(* Logix 5000 project; controller Motion_Axis_AOIs_AMCI_RSLogix_V31 vendor 1 type 14 code 108 rev 31.11; software revision 31.02 *)

TASK MainTask (continuous, watchdog 500 ms) : MainProgram

MODULES
   Local : vendor 1 type 14 code 108 (Compact 0, rev 31.11)
      AMCI_SD31045E2 : vendor 10 type 12 code 27 (Ethernet 192.168.0.53, rev 1.2, StandardDataDriven RPI 8 ms)
      AMCI_SMD23E2 : vendor 10 type 12 code 29 (Ethernet 192.168.0.50, rev 1.6, StandardDataDriven RPI 8 ms)
      AMCI_SMD17E2 : vendor 10 type 12 code 45 (Ethernet 192.168.0.54, rev 1.18, StandardDataDriven RPI 8 ms)
      AMCI_SMD34E2 : vendor 10 type 12 code 28 (Ethernet 192.168.0.55, rev 1.6, StandardDataDriven RPI 8 ms)
      AMCI_SD17060E2 : vendor 10 type 12 code 26 (Ethernet 192.168.0.52, rev 1.2, StandardDataDriven RPI 8 ms)
      AMCI_SD4840E2 : vendor 10 type 12 code 40 (Ethernet 192.168.0.51, rev 1.21, StandardDataDriven RPI 8 ms)
      AMCI_SV160E2 : vendor 10 type 12 code 47 (Ethernet 192.168.0.56, rev 1.31, StandardDataDriven RPI 8 ms)
      AMCI_SV400E2 : vendor 10 type 12 code 51 (Ethernet 192.168.0.57, rev 1.31, StandardDataDriven RPI 8 ms)
END_MODULES

TYPE AMCI_Motion_Axis_Input_Data :
STRUCT
   Moving_CW : BOOL;
   Moving_CCW : BOOL;
   In_Hold_State : BOOL;
   Stopped : BOOL;
   At_Home : BOOL;
   Accelerating : BOOL;
   Decelerating : BOOL;
   Move_Complete : BOOL;
   Status_Word_0_Bit_8 : BOOL;
   Status_Word_0_Bit_9 : BOOL;
   Position_Invalid : BOOL;
   Input_Error : BOOL;
   Command_Error : BOOL;
   Configuration_Error : BOOL;
   Module_OK : BOOL;
   Mode_Flag : BOOL;
   IN1_Active : BOOL;
   IN2_Active : BOOL;
   IN3_Active : BOOL;
   IN4_Active : BOOL;
   Status_Word_1_Bit_4 : BOOL;
   Status_Word_1_Bit_5 : BOOL;
   Connection_Was_Lost : BOOL;
   Driver_Fault : BOOL;
   Status_Word_1_Bit_8 : BOOL;
   Invalid_Jog_Change : BOOL;
   Status_Word_1_Bit_10 : BOOL;
   Heartbeat_Bit : BOOL;
   Status_Word_1_Bit_12 : BOOL;
   Status_Word_1_Bit_13 : BOOL;
   Stall_Detected : BOOL;
   Drive_Is_Enabled : BOOL;
   Motor_Position : DINT;
   Encoder_Position : DINT;
   Trapped_Encoder_Position : DINT;
   Input_Word_8 : INT;
   Input_Word_9 : INT;
END_STRUCT
END_TYPE

TYPE AMCI_Motion_Axis_Output_Data :
STRUCT
   Control_Word_0 : INT;
   Control_Word_1 : INT;
   Position_or_Distance : DINT;
   Programmed_Speed : DINT;
   Acceleration : INT;
   Deceleration : INT;
   Output_Word_8 : INT;
   Output_Word_9 : INT;
END_STRUCT
END_TYPE

ADD_ON_INSTRUCTION AMCI_MA_Preset_Encoder   (* revision 2.1, vendor AMCI, ExecuteEnableInFalse *)
// AMCI Preset Encoder Position.  Will not work on SVXXXE2
// Revision note:
// 3/6/23: Added Save in Flash bit
// 11/17/23 V2.1 Reset output word 0 to 0 when the rung goes false.
// Help:
// MOTION_AXIS_PRESET_ENCODER: Preset Encoder Position to a value.  This AOI will only work on AMCI SD and SMD devices that have an encoder.   This AOI WILL NOT WORK  with SVXXXE2 units
// Note: This instruction will maintain the motion device’s current enabled state.  That is, if the device is enabled,
//            it will remain enabled.  If it is disabled, it will remain disabled.
// AXIS INPUT DATA:  Input data from AMCI motion device.   Uses the AMCI_Motion_Axis_Input_Data User Defined Data Type.
// AXIS OUTPUT DATA; Output data from the AOI to the AMCI motion device.   Uses the AMCI_Motion_Axis_Output_Data User Defined Data Type.
// POSITION: Position to which the Encoder Position is to be set.
// SAVE_IN_FLASH_0_NO_1_YES:  Saves the offset encoder value in the flash memory.    Only used on the SMDXXE2 units with Absolute Encoders.  Must be zero on all other units.
// EN (Enable) Set when rung is true, Reset when rung is false
// DN (Done) Set when command is sent to the motion device.  Reset when the rung is false.
// ER (Error) Set when a command or input error failed to clear.  Reset when the rung is false.
VAR_IN_OUT
   Axis_Input_Data : AMCI_Motion_Axis_Input_Data; {required}
   Axis_Output_Data : AMCI_Motion_Axis_Output_Data; {required}
END_VAR
VAR_INPUT
   Position : DINT; {required}
   save_in_flash_0_no_1_yes : BOOL; {required}
END_VAR
VAR_OUTPUT
   EN : BOOL; {visible}   // set when rung with AOI is true
   DN : BOOL; {access Read Only, visible}   // set when preset motor position command sent to motion axis
   ER : BOOL; {access Read Only, visible}   // set when input, command, or configuraiton error
END_VAR
VAR
   command_data_block : INT[10];
        [2]   // Upper Target Position
        [4]   // Upper Programmed Speed
        [5]   // Lower Programmed Speed
        [1]   // Command Bits LSW
        [0]   // Command Bits MSW
        [3]   // Lower Target Position
END_VAR

ROUTINE EnableInFalse   (* ladder *)
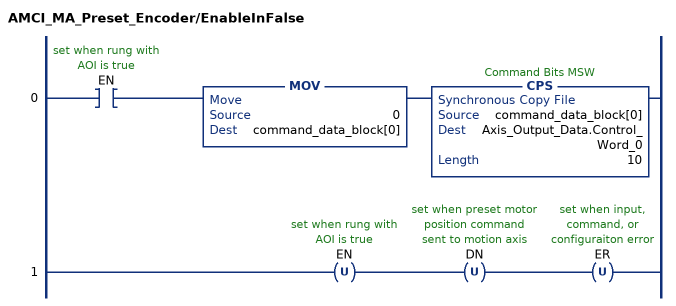
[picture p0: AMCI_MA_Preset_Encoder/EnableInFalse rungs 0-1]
   0: XIC(EN)MOV(0,command_data_block[0])CPS(command_data_block[0],Axis_Output_Data.Control_Word_0,10);
   1: OTU(EN)OTU(DN)OTU(ER);
END_ROUTINE

ROUTINE Logic   (* ladder *)
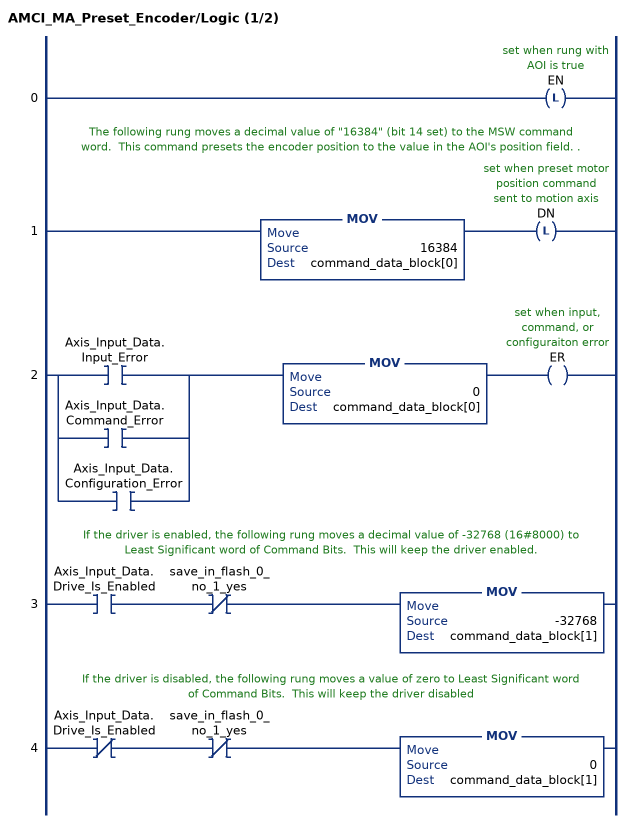
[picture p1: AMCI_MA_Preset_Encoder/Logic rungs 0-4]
   0: OTL(EN);
   // The following rung moves a decimal value of "16384" (bit 14 set) to the MSW command word.  This command presets the encoder position to the value in the AOI's position field. .
   1: MOV(16384,command_data_block[0])OTL(DN);
   2: [XIC(Axis_Input_Data.Input_Error) ,XIC(Axis_Input_Data.Command_Error) ,XIC(Axis_Input_Data.Configuration_Error) ]MOV(0,command_data_block[0])OTE(ER);
   // If the driver is enabled, the following rung moves a decimal value of -32768 (16#8000) to Least Significant word of Command Bits.  This will keep the driver enabled.
   3: XIC(Axis_Input_Data.Drive_Is_Enabled)XIO(save_in_flash_0_no_1_yes)MOV(-32768,command_data_block[1]);
   // If the driver is disabled, the following rung moves a value of zero to Least Significant word of Command Bits.  This will keep the driver disabled
   4: XIO(Axis_Input_Data.Drive_Is_Enabled)XIO(save_in_flash_0_no_1_yes)MOV(0,command_data_block[1]);
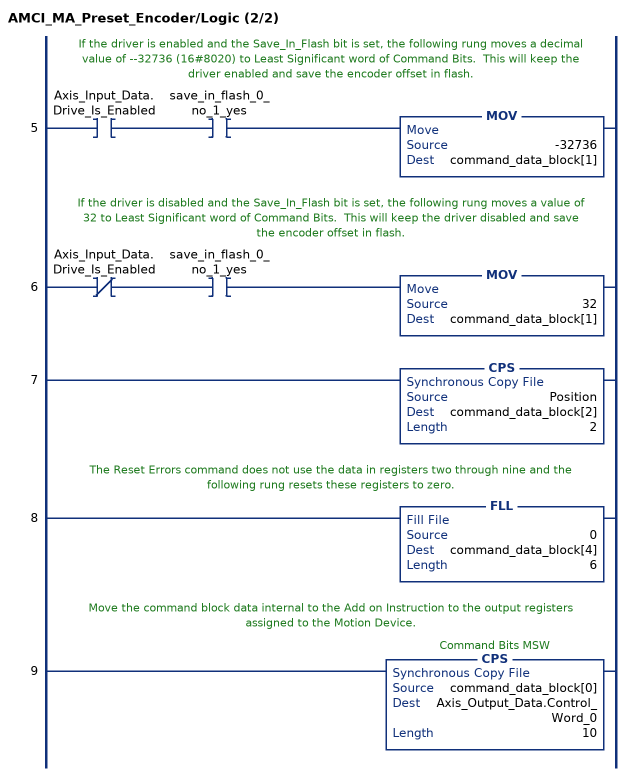
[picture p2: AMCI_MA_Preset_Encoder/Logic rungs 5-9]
   // If the driver is enabled and the Save_In_Flash bit is set, the following rung moves a decimal value of --32736 (16#8020) to Least Significant word of Command Bits.  This will keep the driver enabled and save the encoder offset in flash.
   5: XIC(Axis_Input_Data.Drive_Is_Enabled)XIC(save_in_flash_0_no_1_yes)MOV(-32736,command_data_block[1]);
   // If the driver is disabled and the Save_In_Flash bit is set, the following rung moves a value of 32 to Least Significant word of Command Bits.  This will keep the driver disabled and save the encoder offset in flash.
   6: XIO(Axis_Input_Data.Drive_Is_Enabled)XIC(save_in_flash_0_no_1_yes)MOV(32,command_data_block[1]);
   7: CPS(Position,command_data_block[2],2);
   // The Reset Errors command does not use the data in registers two through nine and the following rung resets these registers to zero.
   8: FLL(0,command_data_block[4],6);
   // Move the command block data internal to the Add on Instruction to the output registers assigned to the Motion Device.
   9: CPS(command_data_block[0],Axis_Output_Data.Control_Word_0,10);
END_ROUTINE
END_ADD_ON_INSTRUCTION

ADD_ON_INSTRUCTION AMCI_MA_Program_Assembed_Move   (* revision 1.0, vendor AMCI, ExecuteEnableInFalse *)
// Program Assembled Moves for SD and SMD devices.  Will not work with SV integrated servo devices.
// Help:
// MOTION AXIS PROGRAM ASSEMBLED MOVE
// This AOIs will only work with the SD and SMD motion devices.  The SV motion devices do not support Assembled Moves.
// Up to 16 segments can be programmed into an Assembled Move.
// AXIS INPUT DATA:  Input data from AMCI motion device.   Uses the AMCI_Motion_Axis_Input_Data User Defined Data Type.
// AXIS OUTPUT DATA; Output data from the AOI to the AMCI motion device.   Uses the AMCI_Motion_Axis_Output_Data User Defined Data Type.
// NUMBER_OF_SEGMENTS: Number of Move segments, range of 2 to 16.
// SEGMENT_X_DISTANCE: The relative number of steps to move in the “X” segment.
// SEGMENT_X_PROGRAMMED_SPEED:   The target speed of the “X” segment
// SEGMENT_X_ACCELERATION: If the programmed speed of the previous segment is less than the                                                      programmed speed of the current segment, the acceleration is used as the                                                      rate of change of the speed between the two segments.
// SEGMENT_X_DECELERATION: If the programmed speed of the previous segment is greater than the                                                       programmed speed of the current segment, the deceleration is used as the                                                       rate of change of the speed between the two segments.
// EN (Enable) Set when rung is true, Reset when rung is false
// ER (Error) Set when a command or input error failed to clear.  Reset when the rung is false.
// ASSEMBLED_MOVE_PROGRAMMED: Set when All segments of the Assembled Move have been                                                                 programmed.  Reset when the rung is false.
VAR_IN_OUT
   Axis_Input_data : AMCI_Motion_Axis_Input_Data; {required}
   Axis_Output_data : AMCI_Motion_Axis_Output_Data; {required}
END_VAR
VAR_INPUT
   Number_of_Segments : DINT; {required}
   Segment_1_Distance : DINT; {required}
   Segment_1_Programmed_Speed : DINT; {required}
   Segment_1_Acceleration : INT; {required}
   Segment_1_Deceleration : INT; {required}
   Segment_2_Distance : DINT; {required}
   Segment_2_Programmed_Speed : DINT; {required}
   Segment_2_Acceleration : INT; {required}
   Segment_2_Deceleration : INT; {required}
   Segment_3_Distance : DINT; {required}
   Segment_3_Programmed_Speed : DINT; {required}
   Segment_3_Acceleration : INT; {required}
   Segment_3_Deceleration : INT; {required}
   Segment_4_Distance : DINT; {required}
   Segment_4_Programmed_Speed : DINT; {required}
   Segment_4_Acceleration : INT; {required}
   Segment_4_Deceleration : INT; {required}
   Segment_5_Distance : DINT; {required}
   Segment_5_Programmed_Speed : DINT; {required}
   Segment_5_Acceleration : INT; {required}
   Segment_5_Deceleration : INT; {required}
   Segment_6_Distance : DINT; {required}
   Segment_6_Programmed_Speed : DINT; {required}
   Segment_6_Acceleration : INT; {required}
   Segment_6_Deceleration : INT; {required}
   Segment_7_Distance : DINT; {required}
   Segment_7_Programmed_Speed : DINT; {required}
   Segment_7_Acceleration : INT; {required}
   Segment_7_Deceleration : INT; {required}
   Segment_8_Distance : DINT; {required}
   Segment_8_Programmed_Speed : DINT; {required}
   Segment_8_Acceleration : INT; {required}
   Segment_8_Deceleration : INT; {required}
   Segment_9_Distance : DINT; {required}
   Segment_9_Programmed_Speed : DINT; {required}
   Segment_9_Acceleration : INT; {required}
   Segment_9_Deceleration : INT; {required}
   Segment_10_Distance : DINT; {required}
   Segment_10_Programmed_Speed : DINT; {required}
   Segment_10_Acceleration : INT; {required}
   Segment_10_Deceleration : INT; {required}
   Segment_11_Distance : DINT; {required}
   Segment_11_Programmed_Speed : DINT; {required}
   Segment_11_Acceleration : INT; {required}
   Segment_11_Deceleration : INT; {required}
   Segment_12_Distance : DINT; {required}
   Segment_12_Programmed_Speed : DINT; {required}
   Segment_12_Acceleration : INT; {required}
   Segment_12_Deceleration : INT; {required}
   Segment_13_Distance : DINT; {required}
   Segment_13_Programmed_Speed : DINT; {required}
   Segment_13_Acceleration : INT; {required}
   Segment_13_Deceleration : INT; {required}
   Segment_14_Distance : DINT; {required}
   Segment_14_Programmed_Speed : DINT; {required}
   Segment_14_Acceleration : INT; {required}
   Segment_14_Deceleration : INT; {required}
   Segment_15_Distance : DINT; {required}
   Segment_15_Programmed_Speed : DINT; {required}
   Segment_15_Acceleration : INT; {required}
   Segment_15_Deceleration : INT; {required}
   Segment_16_Distance : DINT; {required}
   Segment_16_Programmed_Speed : DINT; {required}
   Segment_16_Acceleration : INT; {required}
   Segment_16_Deceleration : INT; {required}
END_VAR
VAR_OUTPUT
   EN : BOOL; {access Read Only, visible}
   ER : BOOL; {access Read Only, visible}
   Assembled_Move_Programmed : BOOL; {access Read Only, visible}
END_VAR
VAR
   command_data_block : INT[10];
        [5]   // Lower Programmed Speed
        [0]   // Command Bits MSW
        [2]   // Upper Target Position
        [4]   // Upper Programmed Speed
        [1]   // Command Bits LSW
        [3]   // Lower Target Position
   Assembled_Move_setup : INT[10] := ([0] := 2048, [1] := -32768); {access None}
   Assembled_Move_counter : COUNTER := (PRE := 5); {access None}
        .ACC   // Controls which segment is sent to the Motion Axis Device
   comment_coil : BOOL; {access None}
END_VAR

ROUTINE EnableInFalse   (* ladder *)
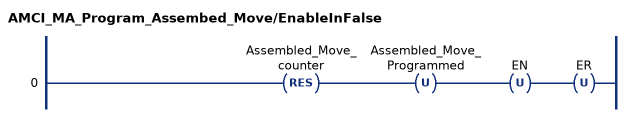
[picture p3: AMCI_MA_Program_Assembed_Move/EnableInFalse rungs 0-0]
   0: RES(Assembled_Move_counter)OTU(Assembled_Move_Programmed)OTU(EN)OTU(ER);
END_ROUTINE

ROUTINE Logic   (* ladder *)
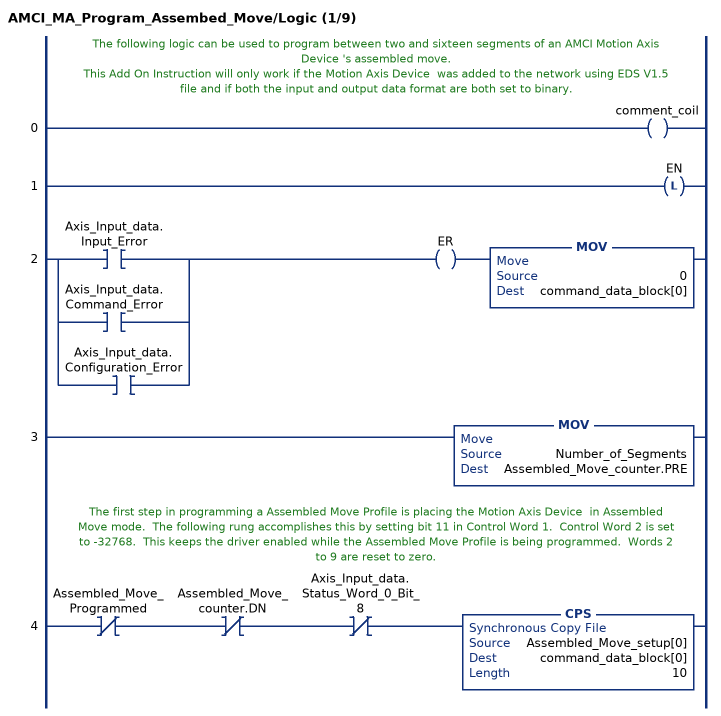
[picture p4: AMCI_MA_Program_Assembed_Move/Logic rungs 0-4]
   // The following logic can be used to program between two and sixteen segments of an AMCI Motion Axis Device 's assembled move.
   // This Add On Instruction will only work if the Motion Axis Device  was added to the network using EDS V1.5 file and if both the input and output data format are both set to binary.
   0: OTE(comment_coil);
   1: OTL(EN);
   2: [XIC(Axis_Input_data.Input_Error) ,XIC(Axis_Input_data.Command_Error) ,XIC(Axis_Input_data.Configuration_Error) ]OTE(ER)MOV(0,command_data_block[0]);
   3: MOV(Number_of_Segments,Assembled_Move_counter.PRE);
   // The first step in programming a Assembled Move Profile is placing the Motion Axis Device  in Assembled Move mode.  The following rung accomplishes this by setting bit 11 in Control Word 1.  Control Word 2 is set to -32768.  This keeps the driver enabled while the Assembled Move Profile is being programmed.  Words 2 to 9 are reset to zero.
   4: XIO(Assembled_Move_Programmed)XIO(Assembled_Move_counter.DN)XIO(Axis_Input_data.Status_Word_0_Bit_8)CPS(Assembled_Move_setup[0],command_data_block[0],10);
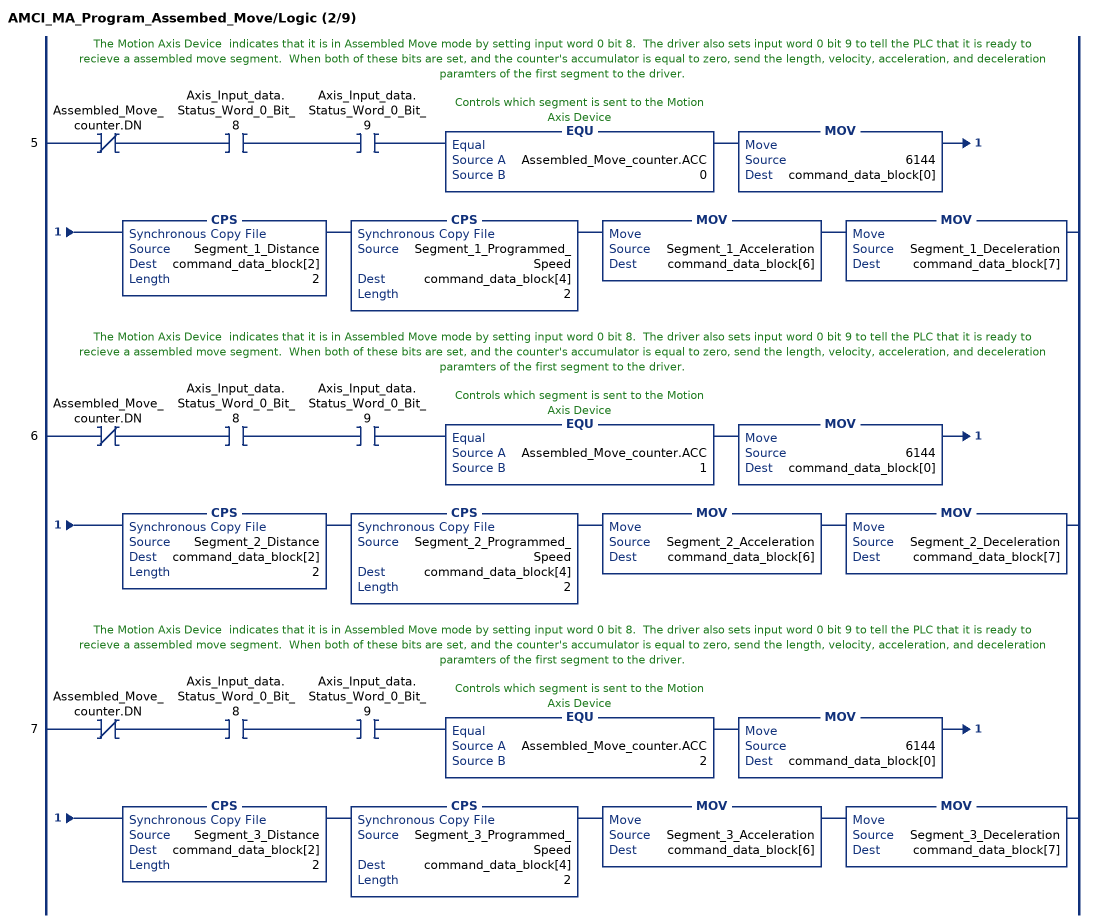
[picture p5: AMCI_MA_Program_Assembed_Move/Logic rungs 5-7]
   // The Motion Axis Device  indicates that it is in Assembled Move mode by setting input word 0 bit 8.  The driver also sets input word 0 bit 9 to tell the PLC that it is ready to recieve a assembled move segment.  When both of these bits are set, and the counter's accumulator is equal to zero, send the length, velocity, acceleration, and deceleration paramters of the first segment to the driver.
   5: XIO(Assembled_Move_counter.DN)XIC(Axis_Input_data.Status_Word_0_Bit_8)XIC(Axis_Input_data.Status_Word_0_Bit_9)EQU(Assembled_Move_counter.ACC,0)MOV(6144,command_data_block[0])CPS(Segment_1_Distance,command_data_block[2],2)CPS(Segment_1_Programmed_Speed,command_data_block[4],2)MOV(Segment_1_Acceleration,command_data_block[6])MOV(Segment_1_Deceleration,command_data_block[7]);
   // The Motion Axis Device  indicates that it is in Assembled Move mode by setting input word 0 bit 8.  The driver also sets input word 0 bit 9 to tell the PLC that it is ready to recieve a assembled move segment.  When both of these bits are set, and the counter's accumulator is equal to zero, send the length, velocity, acceleration, and deceleration paramters of the first segment to the driver.
   6: XIO(Assembled_Move_counter.DN)XIC(Axis_Input_data.Status_Word_0_Bit_8)XIC(Axis_Input_data.Status_Word_0_Bit_9)EQU(Assembled_Move_counter.ACC,1)MOV(6144,command_data_block[0])CPS(Segment_2_Distance,command_data_block[2],2)CPS(Segment_2_Programmed_Speed,command_data_block[4],2)MOV(Segment_2_Acceleration,command_data_block[6])MOV(Segment_2_Deceleration,command_data_block[7]);
   // The Motion Axis Device  indicates that it is in Assembled Move mode by setting input word 0 bit 8.  The driver also sets input word 0 bit 9 to tell the PLC that it is ready to recieve a assembled move segment.  When both of these bits are set, and the counter's accumulator is equal to zero, send the length, velocity, acceleration, and deceleration paramters of the first segment to the driver.
   7: XIO(Assembled_Move_counter.DN)XIC(Axis_Input_data.Status_Word_0_Bit_8)XIC(Axis_Input_data.Status_Word_0_Bit_9)EQU(Assembled_Move_counter.ACC,2)MOV(6144,command_data_block[0])CPS(Segment_3_Distance,command_data_block[2],2)CPS(Segment_3_Programmed_Speed,command_data_block[4],2)MOV(Segment_3_Acceleration,command_data_block[6])MOV(Segment_3_Deceleration,command_data_block[7]);
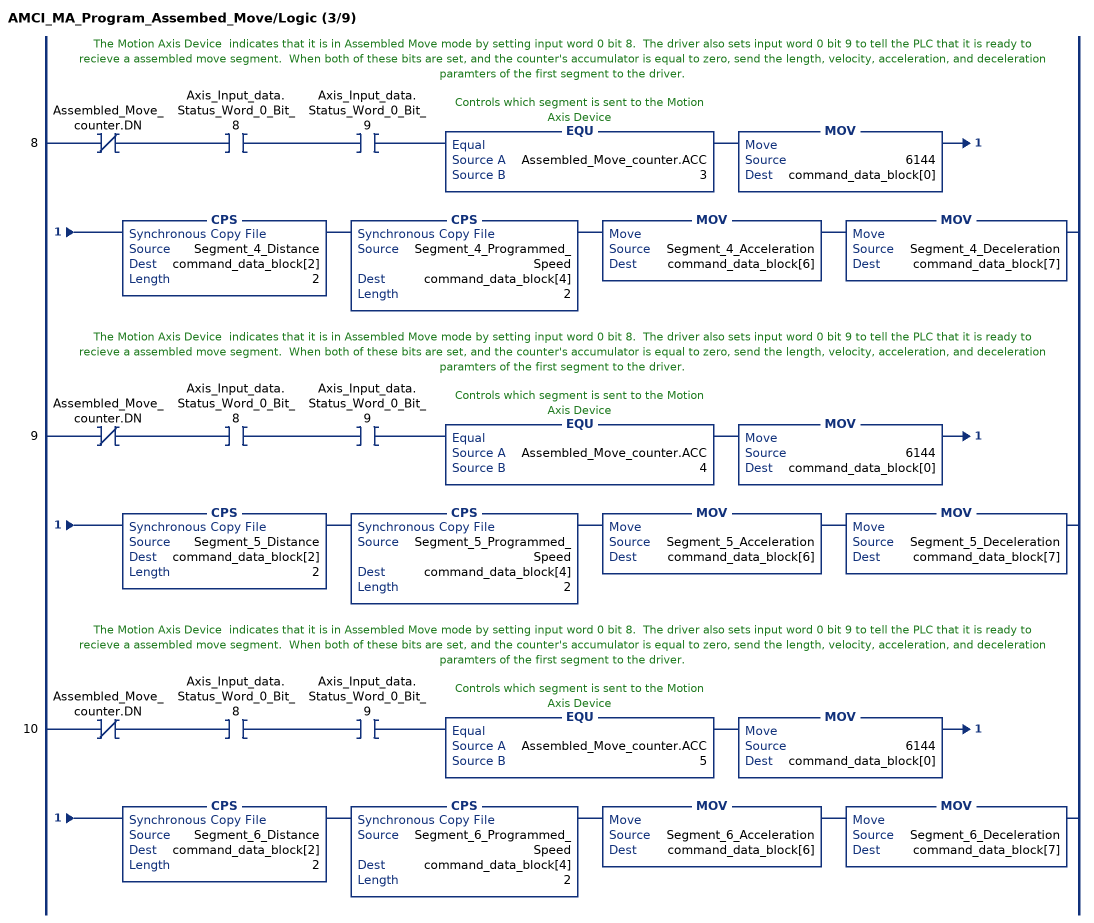
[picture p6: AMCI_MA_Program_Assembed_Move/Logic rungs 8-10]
   // The Motion Axis Device  indicates that it is in Assembled Move mode by setting input word 0 bit 8.  The driver also sets input word 0 bit 9 to tell the PLC that it is ready to recieve a assembled move segment.  When both of these bits are set, and the counter's accumulator is equal to zero, send the length, velocity, acceleration, and deceleration paramters of the first segment to the driver.
   8: XIO(Assembled_Move_counter.DN)XIC(Axis_Input_data.Status_Word_0_Bit_8)XIC(Axis_Input_data.Status_Word_0_Bit_9)EQU(Assembled_Move_counter.ACC,3)MOV(6144,command_data_block[0])CPS(Segment_4_Distance,command_data_block[2],2)CPS(Segment_4_Programmed_Speed,command_data_block[4],2)MOV(Segment_4_Acceleration,command_data_block[6])MOV(Segment_4_Deceleration,command_data_block[7]);
   // The Motion Axis Device  indicates that it is in Assembled Move mode by setting input word 0 bit 8.  The driver also sets input word 0 bit 9 to tell the PLC that it is ready to recieve a assembled move segment.  When both of these bits are set, and the counter's accumulator is equal to zero, send the length, velocity, acceleration, and deceleration paramters of the first segment to the driver.
   9: XIO(Assembled_Move_counter.DN)XIC(Axis_Input_data.Status_Word_0_Bit_8)XIC(Axis_Input_data.Status_Word_0_Bit_9)EQU(Assembled_Move_counter.ACC,4)MOV(6144,command_data_block[0])CPS(Segment_5_Distance,command_data_block[2],2)CPS(Segment_5_Programmed_Speed,command_data_block[4],2)MOV(Segment_5_Acceleration,command_data_block[6])MOV(Segment_5_Deceleration,command_data_block[7]);
   // The Motion Axis Device  indicates that it is in Assembled Move mode by setting input word 0 bit 8.  The driver also sets input word 0 bit 9 to tell the PLC that it is ready to recieve a assembled move segment.  When both of these bits are set, and the counter's accumulator is equal to zero, send the length, velocity, acceleration, and deceleration paramters of the first segment to the driver.
   10: XIO(Assembled_Move_counter.DN)XIC(Axis_Input_data.Status_Word_0_Bit_8)XIC(Axis_Input_data.Status_Word_0_Bit_9)EQU(Assembled_Move_counter.ACC,5)MOV(6144,command_data_block[0])CPS(Segment_6_Distance,command_data_block[2],2)CPS(Segment_6_Programmed_Speed,command_data_block[4],2)MOV(Segment_6_Acceleration,command_data_block[6])MOV(Segment_6_Deceleration,command_data_block[7]);
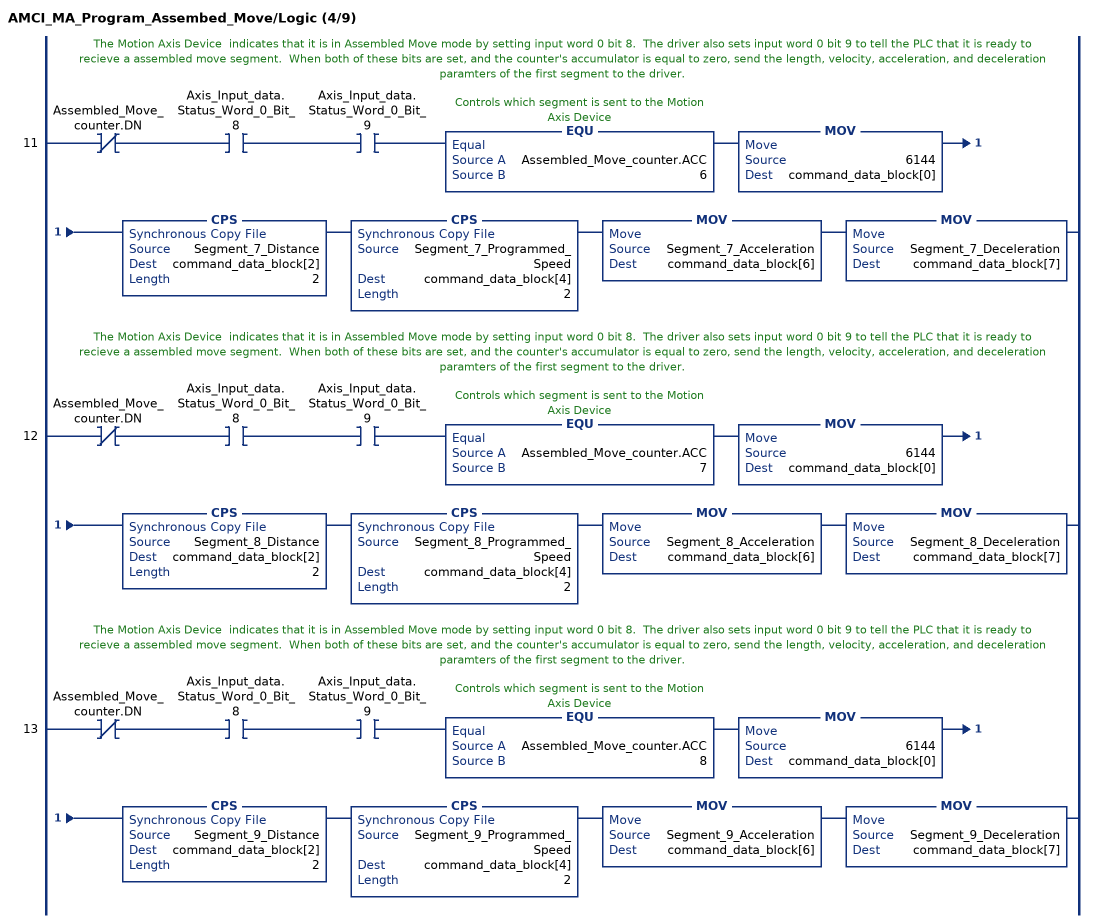
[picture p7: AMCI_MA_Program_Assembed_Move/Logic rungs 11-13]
   // The Motion Axis Device  indicates that it is in Assembled Move mode by setting input word 0 bit 8.  The driver also sets input word 0 bit 9 to tell the PLC that it is ready to recieve a assembled move segment.  When both of these bits are set, and the counter's accumulator is equal to zero, send the length, velocity, acceleration, and deceleration paramters of the first segment to the driver.
   11: XIO(Assembled_Move_counter.DN)XIC(Axis_Input_data.Status_Word_0_Bit_8)XIC(Axis_Input_data.Status_Word_0_Bit_9)EQU(Assembled_Move_counter.ACC,6)MOV(6144,command_data_block[0])CPS(Segment_7_Distance,command_data_block[2],2)CPS(Segment_7_Programmed_Speed,command_data_block[4],2)MOV(Segment_7_Acceleration,command_data_block[6])MOV(Segment_7_Deceleration,command_data_block[7]);
   // The Motion Axis Device  indicates that it is in Assembled Move mode by setting input word 0 bit 8.  The driver also sets input word 0 bit 9 to tell the PLC that it is ready to recieve a assembled move segment.  When both of these bits are set, and the counter's accumulator is equal to zero, send the length, velocity, acceleration, and deceleration paramters of the first segment to the driver.
   12: XIO(Assembled_Move_counter.DN)XIC(Axis_Input_data.Status_Word_0_Bit_8)XIC(Axis_Input_data.Status_Word_0_Bit_9)EQU(Assembled_Move_counter.ACC,7)MOV(6144,command_data_block[0])CPS(Segment_8_Distance,command_data_block[2],2)CPS(Segment_8_Programmed_Speed,command_data_block[4],2)MOV(Segment_8_Acceleration,command_data_block[6])MOV(Segment_8_Deceleration,command_data_block[7]);
   // The Motion Axis Device  indicates that it is in Assembled Move mode by setting input word 0 bit 8.  The driver also sets input word 0 bit 9 to tell the PLC that it is ready to recieve a assembled move segment.  When both of these bits are set, and the counter's accumulator is equal to zero, send the length, velocity, acceleration, and deceleration paramters of the first segment to the driver.
   13: XIO(Assembled_Move_counter.DN)XIC(Axis_Input_data.Status_Word_0_Bit_8)XIC(Axis_Input_data.Status_Word_0_Bit_9)EQU(Assembled_Move_counter.ACC,8)MOV(6144,command_data_block[0])CPS(Segment_9_Distance,command_data_block[2],2)CPS(Segment_9_Programmed_Speed,command_data_block[4],2)MOV(Segment_9_Acceleration,command_data_block[6])MOV(Segment_9_Deceleration,command_data_block[7]);
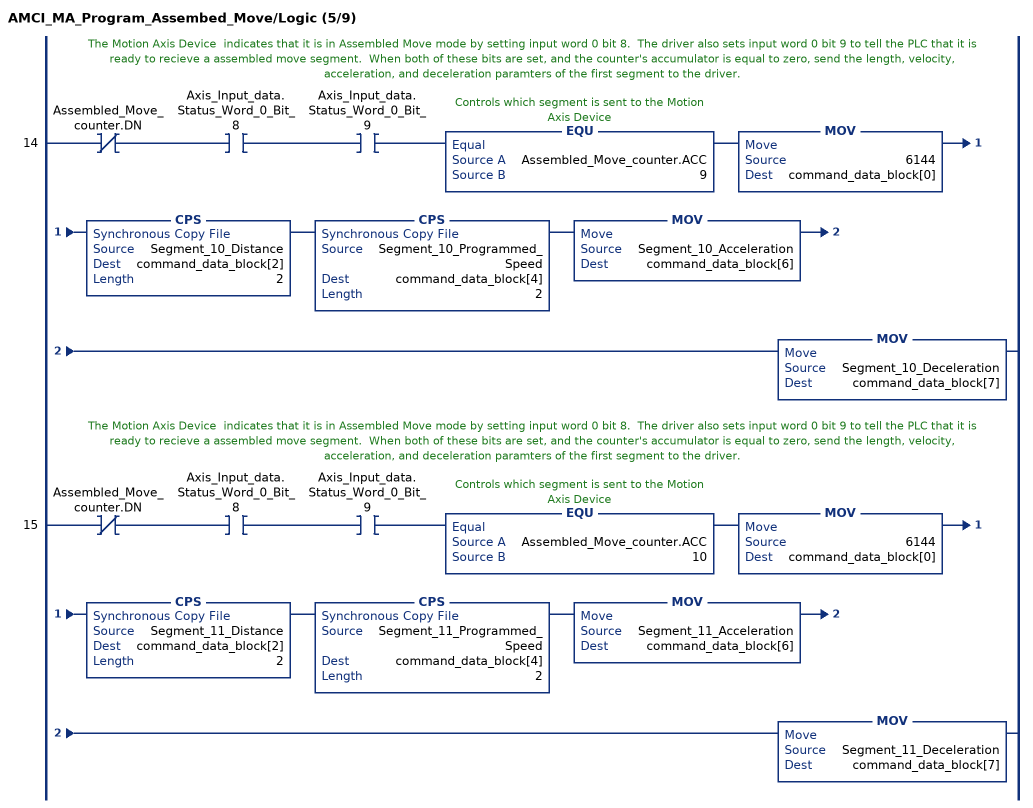
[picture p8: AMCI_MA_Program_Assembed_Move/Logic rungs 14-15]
   // The Motion Axis Device  indicates that it is in Assembled Move mode by setting input word 0 bit 8.  The driver also sets input word 0 bit 9 to tell the PLC that it is ready to recieve a assembled move segment.  When both of these bits are set, and the counter's accumulator is equal to zero, send the length, velocity, acceleration, and deceleration paramters of the first segment to the driver.
   14: XIO(Assembled_Move_counter.DN)XIC(Axis_Input_data.Status_Word_0_Bit_8)XIC(Axis_Input_data.Status_Word_0_Bit_9)EQU(Assembled_Move_counter.ACC,9)MOV(6144,command_data_block[0])CPS(Segment_10_Distance,command_data_block[2],2)CPS(Segment_10_Programmed_Speed,command_data_block[4],2)MOV(Segment_10_Acceleration,command_data_block[6])MOV(Segment_10_Deceleration,command_data_block[7]);
   // The Motion Axis Device  indicates that it is in Assembled Move mode by setting input word 0 bit 8.  The driver also sets input word 0 bit 9 to tell the PLC that it is ready to recieve a assembled move segment.  When both of these bits are set, and the counter's accumulator is equal to zero, send the length, velocity, acceleration, and deceleration paramters of the first segment to the driver.
   15: XIO(Assembled_Move_counter.DN)XIC(Axis_Input_data.Status_Word_0_Bit_8)XIC(Axis_Input_data.Status_Word_0_Bit_9)EQU(Assembled_Move_counter.ACC,10)MOV(6144,command_data_block[0])CPS(Segment_11_Distance,command_data_block[2],2)CPS(Segment_11_Programmed_Speed,command_data_block[4],2)MOV(Segment_11_Acceleration,command_data_block[6])MOV(Segment_11_Deceleration,command_data_block[7]);
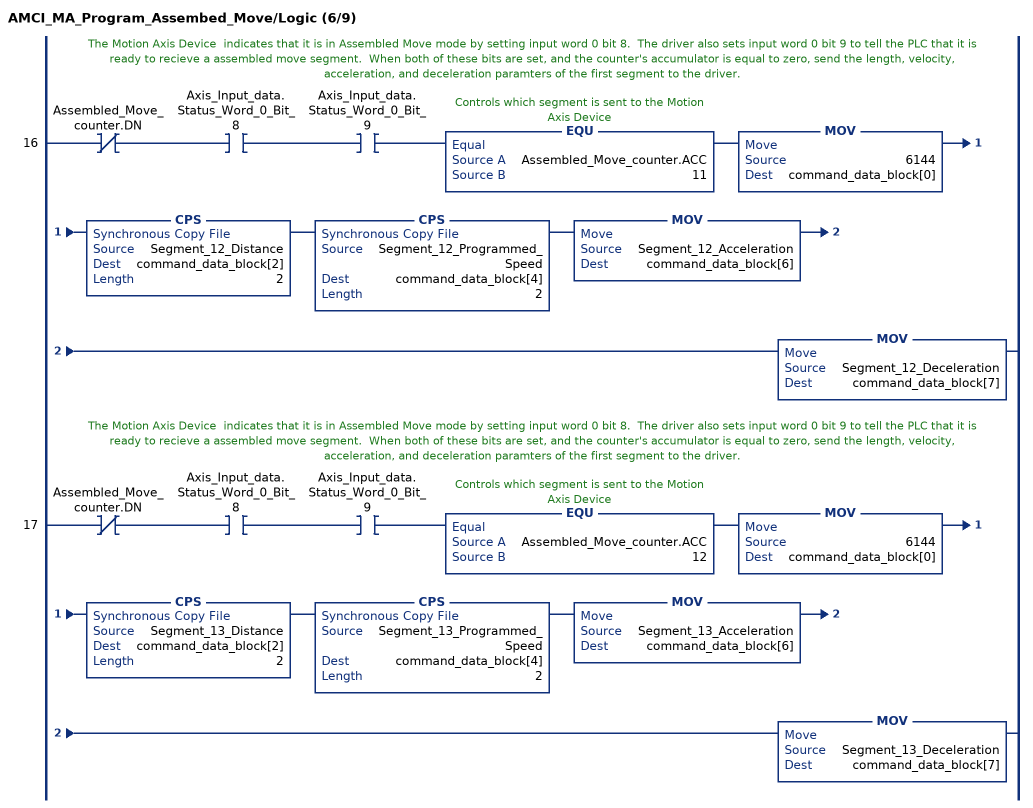
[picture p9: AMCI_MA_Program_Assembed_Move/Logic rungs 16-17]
   // The Motion Axis Device  indicates that it is in Assembled Move mode by setting input word 0 bit 8.  The driver also sets input word 0 bit 9 to tell the PLC that it is ready to recieve a assembled move segment.  When both of these bits are set, and the counter's accumulator is equal to zero, send the length, velocity, acceleration, and deceleration paramters of the first segment to the driver.
   16: XIO(Assembled_Move_counter.DN)XIC(Axis_Input_data.Status_Word_0_Bit_8)XIC(Axis_Input_data.Status_Word_0_Bit_9)EQU(Assembled_Move_counter.ACC,11)MOV(6144,command_data_block[0])CPS(Segment_12_Distance,command_data_block[2],2)CPS(Segment_12_Programmed_Speed,command_data_block[4],2)MOV(Segment_12_Acceleration,command_data_block[6])MOV(Segment_12_Deceleration,command_data_block[7]);
   // The Motion Axis Device  indicates that it is in Assembled Move mode by setting input word 0 bit 8.  The driver also sets input word 0 bit 9 to tell the PLC that it is ready to recieve a assembled move segment.  When both of these bits are set, and the counter's accumulator is equal to zero, send the length, velocity, acceleration, and deceleration paramters of the first segment to the driver.
   17: XIO(Assembled_Move_counter.DN)XIC(Axis_Input_data.Status_Word_0_Bit_8)XIC(Axis_Input_data.Status_Word_0_Bit_9)EQU(Assembled_Move_counter.ACC,12)MOV(6144,command_data_block[0])CPS(Segment_13_Distance,command_data_block[2],2)CPS(Segment_13_Programmed_Speed,command_data_block[4],2)MOV(Segment_13_Acceleration,command_data_block[6])MOV(Segment_13_Deceleration,command_data_block[7]);
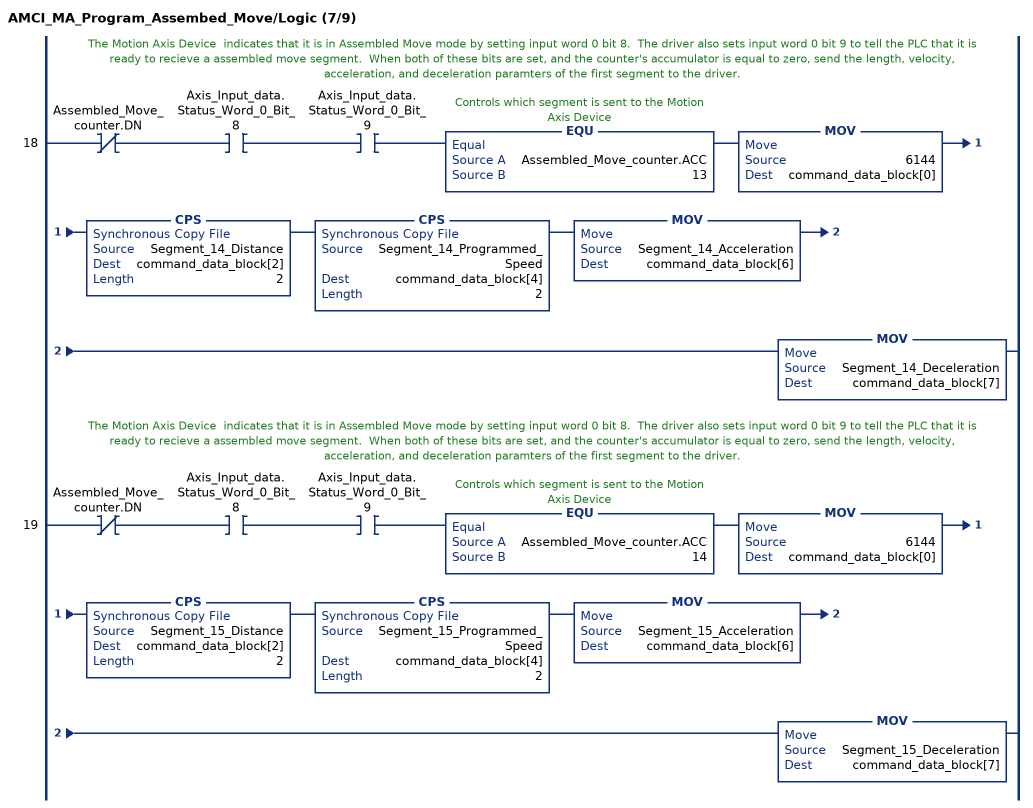
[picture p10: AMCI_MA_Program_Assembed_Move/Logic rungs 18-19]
   // The Motion Axis Device  indicates that it is in Assembled Move mode by setting input word 0 bit 8.  The driver also sets input word 0 bit 9 to tell the PLC that it is ready to recieve a assembled move segment.  When both of these bits are set, and the counter's accumulator is equal to zero, send the length, velocity, acceleration, and deceleration paramters of the first segment to the driver.
   18: XIO(Assembled_Move_counter.DN)XIC(Axis_Input_data.Status_Word_0_Bit_8)XIC(Axis_Input_data.Status_Word_0_Bit_9)EQU(Assembled_Move_counter.ACC,13)MOV(6144,command_data_block[0])CPS(Segment_14_Distance,command_data_block[2],2)CPS(Segment_14_Programmed_Speed,command_data_block[4],2)MOV(Segment_14_Acceleration,command_data_block[6])MOV(Segment_14_Deceleration,command_data_block[7]);
   // The Motion Axis Device  indicates that it is in Assembled Move mode by setting input word 0 bit 8.  The driver also sets input word 0 bit 9 to tell the PLC that it is ready to recieve a assembled move segment.  When both of these bits are set, and the counter's accumulator is equal to zero, send the length, velocity, acceleration, and deceleration paramters of the first segment to the driver.
   19: XIO(Assembled_Move_counter.DN)XIC(Axis_Input_data.Status_Word_0_Bit_8)XIC(Axis_Input_data.Status_Word_0_Bit_9)EQU(Assembled_Move_counter.ACC,14)MOV(6144,command_data_block[0])CPS(Segment_15_Distance,command_data_block[2],2)CPS(Segment_15_Programmed_Speed,command_data_block[4],2)MOV(Segment_15_Acceleration,command_data_block[6])MOV(Segment_15_Deceleration,command_data_block[7]);
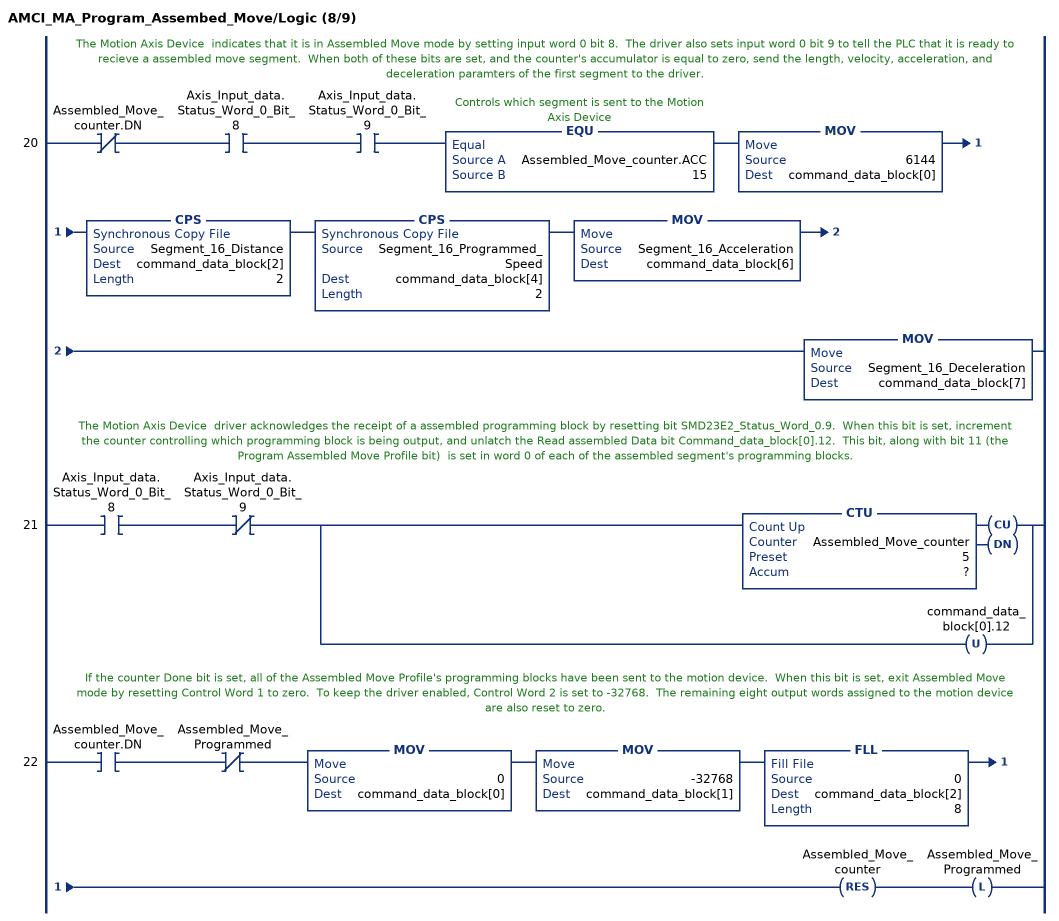
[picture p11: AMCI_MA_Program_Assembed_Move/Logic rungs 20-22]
   // The Motion Axis Device  indicates that it is in Assembled Move mode by setting input word 0 bit 8.  The driver also sets input word 0 bit 9 to tell the PLC that it is ready to recieve a assembled move segment.  When both of these bits are set, and the counter's accumulator is equal to zero, send the length, velocity, acceleration, and deceleration paramters of the first segment to the driver.
   20: XIO(Assembled_Move_counter.DN)XIC(Axis_Input_data.Status_Word_0_Bit_8)XIC(Axis_Input_data.Status_Word_0_Bit_9)EQU(Assembled_Move_counter.ACC,15)MOV(6144,command_data_block[0])CPS(Segment_16_Distance,command_data_block[2],2)CPS(Segment_16_Programmed_Speed,command_data_block[4],2)MOV(Segment_16_Acceleration,command_data_block[6])MOV(Segment_16_Deceleration,command_data_block[7]);
   // The Motion Axis Device  driver acknowledges the receipt of a assembled programming block by resetting bit SMD23E2_Status_Word_0.9.  When this bit is set, increment the counter controlling which programming block is being output, and unlatch the Read assembled Data bit Command_data_block[0].12.  This bit, along with bit 11 (the Program Assembled Move Profile bit)  is set in word 0 of each of the assembled segment's programming blocks.
   21: XIC(Axis_Input_data.Status_Word_0_Bit_8)XIO(Axis_Input_data.Status_Word_0_Bit_9)[CTU(Assembled_Move_counter,?,?) ,OTU(command_data_block[0].12) ];
   // If the counter Done bit is set, all of the Assembled Move Profile's programming blocks have been sent to the motion device.  When this bit is set, exit Assembled Move mode by resetting Control Word 1 to zero.  To keep the driver enabled, Control Word 2 is set to -32768.  The remaining eight output words assigned to the motion device are also reset to zero.
   22: XIC(Assembled_Move_counter.DN)XIO(Assembled_Move_Programmed)MOV(0,command_data_block[0])MOV(-32768,command_data_block[1])FLL(0,command_data_block[2],8)RES(Assembled_Move_counter)OTL(Assembled_Move_Programmed);
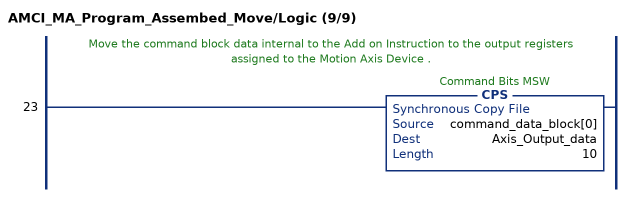
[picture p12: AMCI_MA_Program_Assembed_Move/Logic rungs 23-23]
   // Move the command block data internal to the Add on Instruction to the output registers assigned to the Motion Axis Device .
   23: CPS(command_data_block[0],Axis_Output_data,10);
END_ROUTINE
END_ADD_ON_INSTRUCTION

ADD_ON_INSTRUCTION AMCI_MA_Registration_Move   (* revision 1.0, vendor AMCI, ExecuteEnableInFalse *)
// AMCI Motion Axis Registration Move
// Revision note:
// 12/01/2022 Initial release of AOI.
// Help:
// MOTION AXIS REGISTRATION MOVE
// AXIS INPUT DATA:  Input data from AMCI motion device.   Uses the AMCI_Motion_Axis_Input_Data User Defined Data Type.
// AXIS OUTPUT DATA; Output data from the AOI to the AMCI motion device.   Uses the AMCI_Motion_Axis_Output_Data User Defined Data Type.
// DIRECTION: 0 = CW motion 1 = CCW motion
// STOPPING_DISTANCE: The number of steps to move after the registration input has become active.
// PROGRAMMED SPEED: Speed of move in units of steps / sec
// ACCELERATION: Acceleration Rate in units of steps / sec / ms
// DECELERATION:  Deceleration Rate in units of steps / sec / ms
// MINIMUM REGISTRATION DISTANCE: The number of steps to move during which the registration input is                                                                   ignored.
// EN (Enable) Set when rung is true, Reset when rung is false
// DN (Done) Set when command is sent to the motion device.  Reset when the rung is false.
// ER (Error) Set when a command or input error failed to clear.  Reset when the rung is false.
// IP (In Process) Set when motion is occurring.   Reset when motion stops or the rung goes false.
VAR_IN_OUT
   Axis_Input_Data : AMCI_Motion_Axis_Input_Data; {required}
   Axis_Output_Data : AMCI_Motion_Axis_Output_Data; {required}
END_VAR
VAR_INPUT
   Direction_0_CW_1_CCW : BOOL; {required}   // 0=jog CW 1=jog CCW
   Stopping_Distance : DINT; {required}
   Programmed_Speed : DINT; {required}
   Acceleration : INT; {required}
   Deceleration : INT; {required}
   Minimum_Registration_Distance : DINT; {required}
END_VAR
VAR_OUTPUT
   EN : BOOL; {visible}   // set when rung with AOI is true
   DN : BOOL; {access Read Only, visible}   // set when move was succesfully initiated
   ER : BOOL; {visible}
   IP : BOOL; {visible}   // set when motion occurring
END_VAR
VAR
   command_data_block : INT[10];
        [1]   // Command Bits LSW
        [3]   // Lower Target Position
        [5]   // Lower Programmed Speed
        [0]   // Command Bits MSW
        [2]   // Upper Target Position
        [4]   // Upper Programmed Speed
   motion_occurring : BOOL; {access None}
   Internal_Enable : BOOL; {access None}   // set when driver ready to receive motion command
END_VAR

ROUTINE EnableInFalse   (* ladder *)
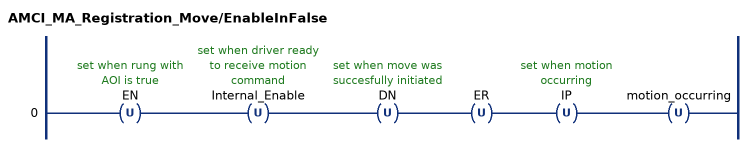
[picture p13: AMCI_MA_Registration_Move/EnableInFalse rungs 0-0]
   0: OTU(EN)OTU(Internal_Enable)OTU(DN)OTU(ER)OTU(IP)OTU(motion_occurring);
END_ROUTINE

ROUTINE Logic   (* ladder *)
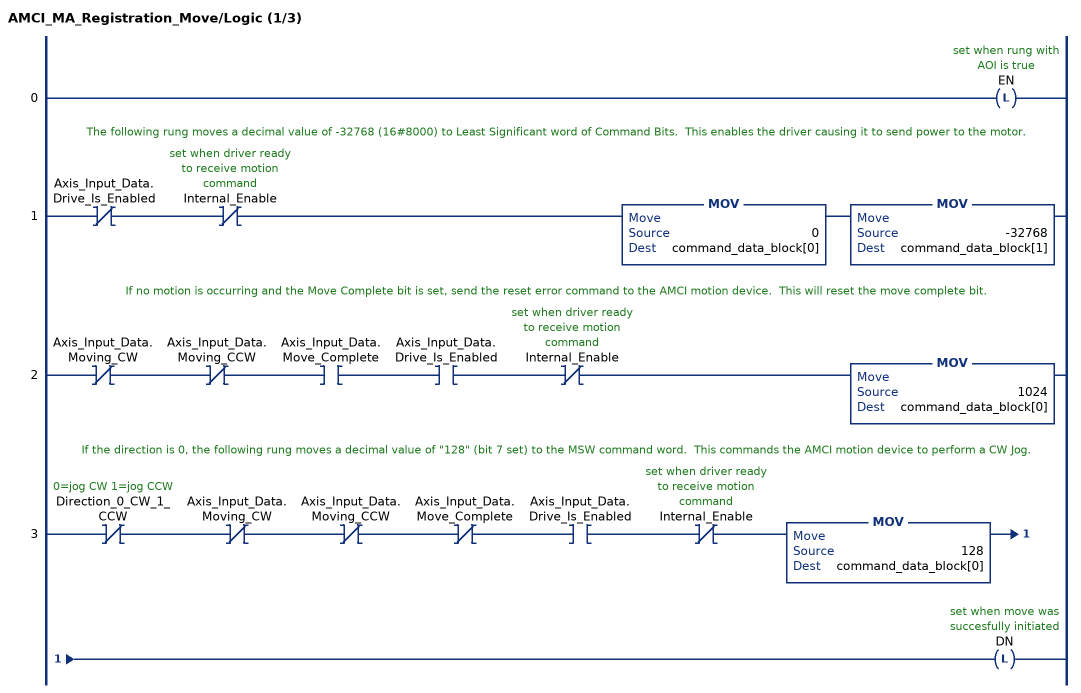
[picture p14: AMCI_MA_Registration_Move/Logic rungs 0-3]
   0: OTL(EN);
   // The following rung moves a decimal value of -32768 (16#8000) to Least Significant word of Command Bits.  This enables the driver causing it to send power to the motor.
   1: XIO(Axis_Input_Data.Drive_Is_Enabled)XIO(Internal_Enable)MOV(0,command_data_block[0])MOV(-32768,command_data_block[1]);
   // If no motion is occurring and the Move Complete bit is set, send the reset error command to the AMCI motion device.  This will reset the move complete bit.
   2: XIO(Axis_Input_Data.Moving_CW)XIO(Axis_Input_Data.Moving_CCW)XIC(Axis_Input_Data.Move_Complete)XIC(Axis_Input_Data.Drive_Is_Enabled)XIO(Internal_Enable)MOV(1024,command_data_block[0]);
   // If the direction is 0, the following rung moves a decimal value of "128" (bit 7 set) to the MSW command word.  This commands the AMCI motion device to perform a CW Jog.
   3: XIO(Direction_0_CW_1_CCW)XIO(Axis_Input_Data.Moving_CW)XIO(Axis_Input_Data.Moving_CCW)XIO(Axis_Input_Data.Move_Complete)XIC(Axis_Input_Data.Drive_Is_Enabled)XIO(Internal_Enable)MOV(128,command_data_block[0])OTL(DN);
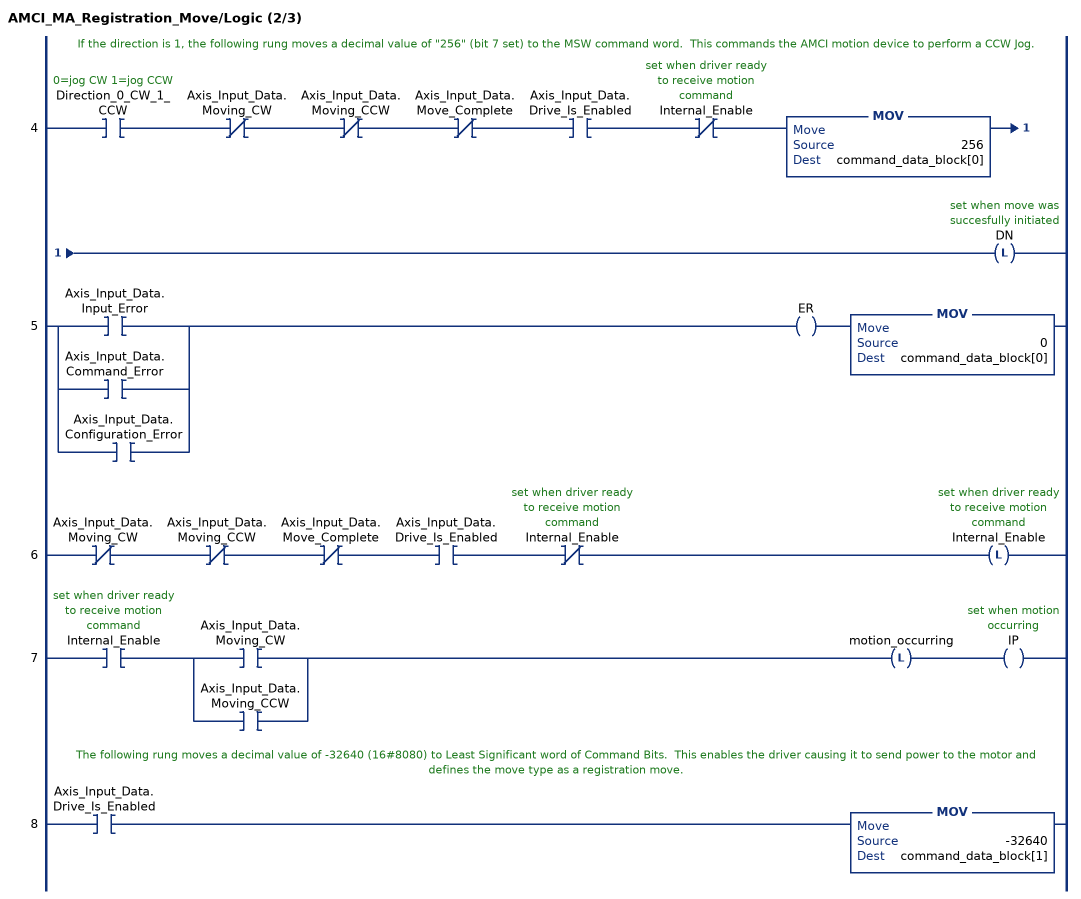
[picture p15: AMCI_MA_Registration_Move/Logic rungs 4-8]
   // If the direction is 1, the following rung moves a decimal value of "256" (bit 7 set) to the MSW command word.  This commands the AMCI motion device to perform a CCW Jog.
   4: XIC(Direction_0_CW_1_CCW)XIO(Axis_Input_Data.Moving_CW)XIO(Axis_Input_Data.Moving_CCW)XIO(Axis_Input_Data.Move_Complete)XIC(Axis_Input_Data.Drive_Is_Enabled)XIO(Internal_Enable)MOV(256,command_data_block[0])OTL(DN);
   5: [XIC(Axis_Input_Data.Input_Error) ,XIC(Axis_Input_Data.Command_Error) ,XIC(Axis_Input_Data.Configuration_Error) ]OTE(ER)MOV(0,command_data_block[0]);
   6: XIO(Axis_Input_Data.Moving_CW)XIO(Axis_Input_Data.Moving_CCW)XIO(Axis_Input_Data.Move_Complete)XIC(Axis_Input_Data.Drive_Is_Enabled)XIO(Internal_Enable)OTL(Internal_Enable);
   7: XIC(Internal_Enable)[XIC(Axis_Input_Data.Moving_CW) ,XIC(Axis_Input_Data.Moving_CCW) ]OTL(motion_occurring)OTE(IP);
   // The following rung moves a decimal value of -32640 (16#8080) to Least Significant word of Command Bits.  This enables the driver causing it to send power to the motor and defines the move type as a registration move.
   8: XIC(Axis_Input_Data.Drive_Is_Enabled)MOV(-32640,command_data_block[1]);
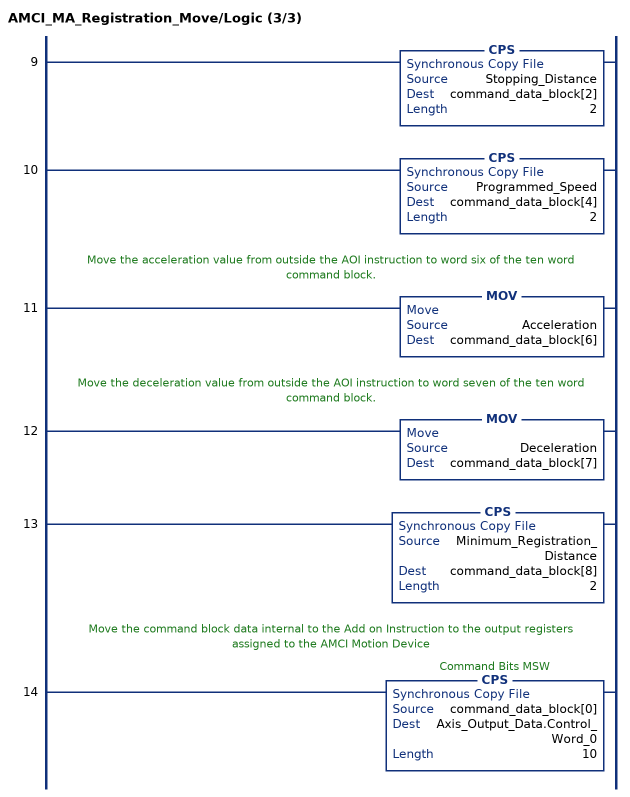
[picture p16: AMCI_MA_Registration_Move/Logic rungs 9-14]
   9: CPS(Stopping_Distance,command_data_block[2],2);
   10: CPS(Programmed_Speed,command_data_block[4],2);
   // Move the acceleration value from outside the AOI instruction to word six of the ten word command block.
   11: MOV(Acceleration,command_data_block[6]);
   // Move the deceleration value from outside the AOI instruction to word seven of the ten word command block.
   12: MOV(Deceleration,command_data_block[7]);
   13: CPS(Minimum_Registration_Distance,command_data_block[8],2);
   // Move the command block data internal to the Add on Instruction to the output registers assigned to the AMCI Motion Device
   14: CPS(command_data_block[0],Axis_Output_Data.Control_Word_0,10);
END_ROUTINE
END_ADD_ON_INSTRUCTION

ADD_ON_INSTRUCTION AMCI_MA_Reset_Driver_Fault   (* revision 1.0, vendor AMCI, ExecuteEnableInFalse *)
// AMCI Reset Driver Faults.   Only for SDXXXXE2 and SMDXXE2 units.
// Help:
// MOTION AXIS RESET DRIVER FAULTS
// This AOI will only work with SMD34E2, SD4840E2, SD17060E2, and SMD31045E2 units.  This AOI WILL NOT WORK with SV160E2 and SV400E2 units.
// AXIS INPUT DATA:  Input data from AMCI motion device.   Uses the AMCI_Motion_Axis_Input_Data User Defined Data Type.
// AXIS OUTPUT DATA; Output data from the AOI to the AMCI motion device.   Uses the AMCI_Motion_Axis_Output_Data User Defined Data Type.
// EN (Enable) Set when rung is true, Reset when rung is false
// DN (Done) Set when command is sent to the motion device.  Reset when the rung is false.
// ER (Error)  The driver fault  failed to clear.  Reset when the rung is false.
VAR_IN_OUT
   Axis_Input_Data : AMCI_Motion_Axis_Input_Data; {required}
   Axis_Output_Data : AMCI_Motion_Axis_Output_Data; {required}
END_VAR
VAR_OUTPUT
   EN : BOOL; {visible}   // set when rung with AOI is true
   DN : BOOL; {access Read Only, visible}   // set when reset error command sent to motion axis
   ER : BOOL; {access Read Only, visible}   // set when reset error command did not clear the driver fault
END_VAR
VAR
   command_data_block : INT[10];
        [1]   // Command Bits LSW
        [3]   // Lower Target Position
        [5]   // Lower Programmed Speed
        [0]   // Command Bits MSW
        [2]   // Upper Target Position
        [4]   // Upper Programmed Speed
   Initialize_timer : TIMER := (PRE := 100); {access None}
END_VAR

ROUTINE EnableInFalse   (* ladder *)
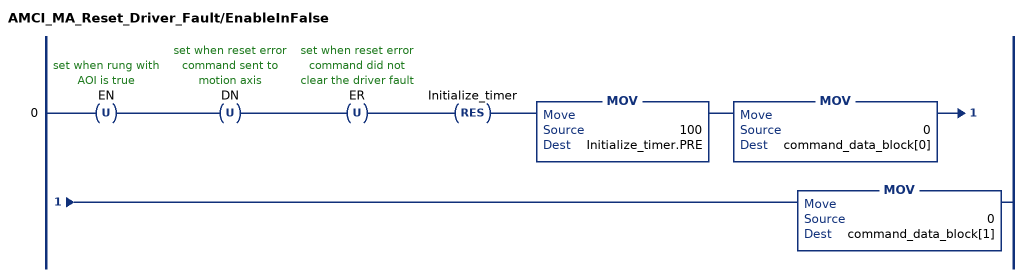
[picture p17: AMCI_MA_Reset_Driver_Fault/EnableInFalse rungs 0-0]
   0: OTU(EN)OTU(DN)OTU(ER)RES(Initialize_timer)MOV(100,Initialize_timer.PRE)MOV(0,command_data_block[0])MOV(0,command_data_block[1]);
END_ROUTINE
